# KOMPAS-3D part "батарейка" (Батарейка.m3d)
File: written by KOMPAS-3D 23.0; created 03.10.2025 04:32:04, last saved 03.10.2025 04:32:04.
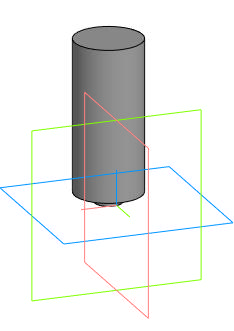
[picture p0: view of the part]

Document properties: Автор: Inspektor_Kot; Полное имя файла: I:\Autodesk Inventor Projects\ИМ-ИТ ЦД\Вариант 14\батарейка.m3d

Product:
- Part/product: батарейка

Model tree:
1. Эскиз:1  (with: Элемент вращения:1)
2. Элемент выдавливания:1
     Расстояние 1 = 45
3. Эскиз:2  (with: Элемент выдавливания:1, Элемент вращения:1)
4. Элемент выдавливания:2
     Расстояние 1 = 3

Referenced files in I:\Autodesk Inventor Projects\ИМ-ИТ ЦД\Вариант 14\: Фонарик.a3d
